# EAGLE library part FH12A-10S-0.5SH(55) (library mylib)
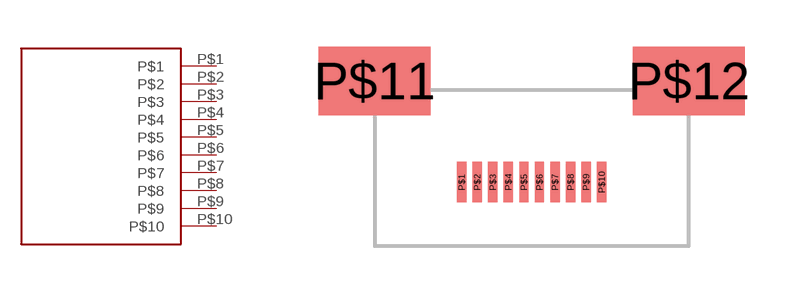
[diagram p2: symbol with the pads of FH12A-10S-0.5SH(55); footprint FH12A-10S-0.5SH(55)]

Designator prefix -

## FH12A-10S-0.5SH(55)  [FH12A-10S-0.5SH(55)]
P$1  P$1
P$2  P$2
P$3  P$3
P$4  P$4
P$5  P$5
P$6  P$6
P$7  P$7
P$8  P$8
P$9  P$9
P$10  P$10

## Footprint FH12A-10S-0.5SH(55) (pad centres in mm)
smd 0.3 x 1.3: P$1 -2.25,0; P$2 -1.75,0; P$3 -1.25,0; P$4 -0.75,0; P$5 -0.25,0; P$6 0.25,0; P$7 0.75,0; P$8 1.25,0; P$9 1.75,0; P$10 2.25,0
smd 3.6 x 2.2: P$11 -5.05,3.25; P$12 5.05,3.25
